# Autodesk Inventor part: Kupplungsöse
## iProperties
Created: 2003-04
Part Number: Kupplungsöse
Material: Aluminium
Document SubType Name: Modellieren
Designer: Administrator
Control State: 0
Master: False
Checked Out: False
Shininess: 20.0
Angle Display Precision: 2
Document Length Units: 11269
Document Angle Units: 11279
Document Time Units: 11290
Document Mass Units: 11283
Document Length Units Precision: 3
Document Angle Units Precision: 2
Density: 0.0
Volumn: 0.0
Area: 0.0
PropertySet Name: Model Information
Author: Administrator
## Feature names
1. Grundkörper [Extrusion]
2. Fase unten außen [Chamfer]
3. Stiftlochbohrung d2 [Hole]
4. Rundung1 [Fillet]
5. Fase oben innen [Extrusion]
